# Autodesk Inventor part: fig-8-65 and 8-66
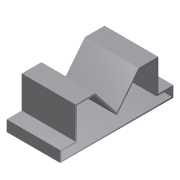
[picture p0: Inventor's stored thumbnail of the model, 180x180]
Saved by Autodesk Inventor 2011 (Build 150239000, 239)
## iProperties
Shininess: 77.0
Length Units: 11269
Angle Units: 11279
Time Units: 11290
Mass Units: 11283
Length Display Precision: 3
Angle Display Precision: 2
Created: 2002-01
Part Number: fig-8-65 and 8-66
Document SubType Name: Modeling
Designer: ***
Density: 1 g/cm^3
Density: 0.0
Volumn: 0.0
Area: 0.0
PropertySet Name: Model Information
Control State: 0
Master: False
Checked Out: False
Author: ***
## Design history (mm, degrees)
node "Sketch1"
sketch "Sketch2"
  geometry: L1 (0, 0)-(-14.184, 17.961); L2 (-14.184, 17.961)-(-26.987, 17.961); L3 (-26.987, 17.961)-(-26.987, -2.947); L4 (-26.987, -2.947)-(-36.842, -2.947); L5 (-36.842, -2.947)-(-36.842, -10.132); L6 (26.987, 17.961)-(26.987, -2.947); L7 (14.184, 17.961)-(26.987, 17.961); L8 (26.987, -2.947)-(36.842, -2.947); L9 (36.842, -10.132)-(-36.842, -10.132); L10 (36.842, -2.947)-(36.842, -10.132); L11 (0, 0)-(14.184, 17.961)
  constraints: 22 end point, 2 horizontal, 2 parallel, 1 perpendicular
extrude "Extrusion1" new body sketch "Sketch2" distance "d0" = 35; taper "d1" = 0 deg
shell "Shell3" dims "d13" = 1
body "Solid1"
